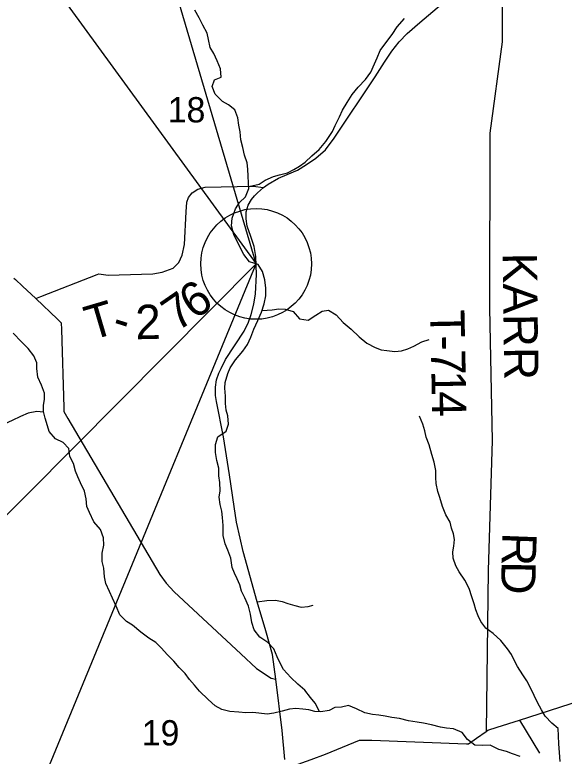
# Model space of a CAD drawing. Extents: x 0 to 34, y 0 to 22.
# Drawn here: x 4.921 to 5.831, y 16.276 to 17.503 of the extents above; entities that cross this region are included whole.
import ezdxf

# ---------------------------------------------------------------- set-up
doc = ezdxf.new("R2010")
doc.units = 0
for name, color, linetype in [('GM_X_County_Road', 7, 'Continuous'), ('GM_X_Minor_River', 7, 'Continuous'), ('GM_X_Section_Text', 7, 'Continuous'), ('GM_X_State_Route', 7, 'Continuous'), ('GM_X_Township_Road', 7, 'Continuous'), ('GM_X_Township_Road_Text', 7, 'Continuous'), ('SH_Text', 7, 'Continuous')]:
    doc.layers.add(name, color=color, linetype=linetype)

msp = doc.modelspace()

# ---------------------------------------------------------------- linework, layer by layer
at = {"layer": 'GM_X_County_Road'}
msp.add_lwpolyline([(5.3691, 16.2545), (5.3828, 16.2597), (5.4119, 16.2704), (5.4359, 16.279), (5.4923, 16.3023), (5.5127, 16.3023), (5.6694, 16.2963), (5.6728, 16.2962), (5.686, 16.3055), (5.702, 16.3168), (5.7051, 16.3189), (5.7202, 16.3238), (5.7575, 16.3358), (6.0466, 16.4289), (6.0506, 16.4302), (6.0602, 16.4422), (6.1578, 16.5648), (6.1712, 16.5792), (6.2848, 16.701), (6.2915, 16.7083)], dxfattribs=at)
at = {"layer": 'GM_X_Minor_River'}
for points in [[(5.4257, 16.3497), (5.4187, 16.3637), (5.4111, 16.3732), (5.4017, 16.385), (5.39, 16.3953), (5.3783, 16.4063), (5.3663, 16.4196), (5.361, 16.4302), (5.3558, 16.4405), (5.3505, 16.4534), (5.3403, 16.4644), (5.3268, 16.4728), (5.3177, 16.4854), (5.3136, 16.4975), (5.3114, 16.5112), (5.3084, 16.5245), (5.302, 16.5381), (5.2964, 16.5491), (5.2938, 16.5598), (5.2897, 16.5696), (5.2848, 16.5791), (5.281, 16.5886), (5.2788, 16.6038), (5.274, 16.6171), (5.2698, 16.6273), (5.2665, 16.6414), (5.2665, 16.6577), (5.2654, 16.6709), (5.264, 16.6816), (5.2614, 16.6926), (5.2595, 16.7047), (5.2611, 16.7153), (5.2607, 16.7293), (5.2593, 16.74), (5.2589, 16.7528), (5.2556, 16.7654), (5.2537, 16.779), (5.2534, 16.7919), (5.2572, 16.8048), (5.2713, 16.8138), (5.2751, 16.8259), (5.274, 16.8392), (5.2714, 16.8487), (5.2699, 16.8597), (5.27, 16.8722), (5.2689, 16.8851), (5.2697, 16.8946), (5.2739, 16.9093), (5.2781, 16.9192), (5.2865, 16.9324), (5.299, 16.9468), (5.3066, 16.9574), (5.3123, 16.9695), (5.3173, 16.9831), (5.3238, 16.9971), (5.3299, 17.0111), (5.3345, 17.0251), (5.3372, 17.0384), (5.3372, 17.0509), (5.3354, 17.0645), (5.3313, 17.0782), (5.3241, 17.09), (5.3101, 17.0946), (5.3004, 17.1067), (5.2958, 17.1162), (5.2842, 17.1398), (5.2801, 17.1538), (5.2813, 17.1667), (5.287, 17.1822), (5.2931, 17.1928), (5.3034, 17.2019), (5.3087, 17.2159), (5.3084, 17.2254), (5.3076, 17.2364), (5.3069, 17.2481), (5.3058, 17.2583), (5.3017, 17.2713), (5.2991, 17.2838), (5.2954, 17.2963), (5.2943, 17.3096), (5.2924, 17.3209), (5.2906, 17.3327), (5.2857, 17.346), (5.2752, 17.3544), (5.2653, 17.3597), (5.2533, 17.3723), (5.248, 17.3848), (5.2522, 17.3958), (5.2628, 17.4003), (5.2621, 17.4139), (5.2561, 17.4272), (5.2509, 17.4394), (5.2449, 17.4496), (5.2419, 17.4625), (5.24, 17.4732), (5.2325, 17.4861), (5.2265, 17.4986), (5.2194, 17.5111)], [(5.3086, 17.2192), (5.3261, 17.223), (5.336, 17.2294), (5.3496, 17.2358), (5.3595, 17.2384), (5.3731, 17.2418), (5.3833, 17.2474), (5.3928, 17.2531), (5.4023, 17.2595), (5.4133, 17.2697), (5.4255, 17.2806), (5.4365, 17.2939), (5.4475, 17.3101), (5.4521, 17.3203), (5.4593, 17.3347), (5.4639, 17.3453), (5.4719, 17.3582), (5.4799, 17.3714), (5.4901, 17.3839), (5.5019, 17.3963), (5.511, 17.4084), (5.5168, 17.4224), (5.5213, 17.4323), (5.5267, 17.4444), (5.5358, 17.4569), (5.5461, 17.4708), (5.5548, 17.4837), (5.5666, 17.4973)], [(5.3308, 17.014), (5.3473, 17.0148), (5.3587, 17.0167), (5.3689, 17.0163), (5.3825, 17.012), (5.393, 16.9999), (5.407, 16.9979), (5.4199, 17.0062), (5.4305, 17.013), (5.4411, 17.0145), (5.4536, 17.0068), (5.4652, 16.9939), (5.4785, 16.9829), (5.4916, 16.9703), (5.5045, 16.9596), (5.5181, 16.9524), (5.5279, 16.9486), (5.5377, 16.9474), (5.5509, 16.9458), (5.5619, 16.9473), (5.5721, 16.9503), (5.5824, 16.9548), (5.5956, 16.9619), (5.6074, 16.9661)], [(5.0255, 16.7382), (5.0217, 16.7481), (5.018, 16.7606), (5.012, 16.7724), (5.0105, 16.7853), (5.0011, 16.7951), (4.9883, 16.8013), (4.9777, 16.8134), (4.9751, 16.8229), (4.9714, 16.8358), (4.9684, 16.8464), (4.9688, 16.8563), (4.97, 16.8673), (4.97, 16.8768), (4.9651, 16.8901), (4.9591, 16.9037), (4.9577, 16.9178), (4.9573, 16.9272), (4.9524, 16.939), (4.943, 16.9508), (4.9321, 16.9618), (4.9185, 16.9763)], [(4.9687, 16.8454), (4.9574, 16.8465), (4.9434, 16.8439), (4.9305, 16.8386), (4.9169, 16.8319), (4.9032, 16.8255), (4.8934, 16.8202), (4.8812, 16.8134), (4.8661, 16.8048), (4.8555, 16.798), (4.8456, 16.7916), (4.8331, 16.7852), (4.8191, 16.7773), (4.8088, 16.7731), (4.7956, 16.7637), (4.78, 16.7547), (4.7705, 16.7509), (4.7577, 16.7449), (4.7467, 16.7427), (4.7221, 16.7371), (4.7119, 16.736), (4.7005, 16.7364)], [(5.825, 16.267), (5.8235, 16.2822), (5.8224, 16.2962), (5.8221, 16.3098), (5.8214, 16.3216), (5.8112, 16.3307), (5.7999, 16.3421), (5.7939, 16.3524), (5.7871, 16.3649), (5.7819, 16.3763), (5.7762, 16.3881), (5.7695, 16.4006), (5.7631, 16.4105), (5.7541, 16.4242), (5.7492, 16.4337), (5.7439, 16.4443), (5.7375, 16.4538), (5.7266, 16.4675), (5.7138, 16.4789), (5.7017, 16.4881), (5.6934, 16.4987), (5.6889, 16.5082), (5.6852, 16.5181), (5.6822, 16.5283), (5.6781, 16.5397), (5.674, 16.5534), (5.6668, 16.5671), (5.6574, 16.5811), (5.6518, 16.591), (5.6477, 16.6039), (5.6469, 16.6141), (5.6485, 16.6236), (5.6497, 16.6346), (5.6478, 16.6441), (5.6448, 16.6536), (5.6422, 16.6634), (5.6351, 16.6756), (5.6298, 16.6896), (5.6253, 16.7041), (5.6223, 16.7143), (5.619, 16.7272), (5.6186, 16.7371), (5.6187, 16.7488), (5.6161, 16.7625), (5.612, 16.7754), (5.6075, 16.7913), (5.6026, 16.8042), (5.6004, 16.8145), (5.5974, 16.8258), (5.5918, 16.8388)], [(5.7584, 16.2752), (5.7456, 16.2798), (5.7358, 16.2836), (5.7233, 16.2871), (5.7089, 16.2943), (5.6961, 16.2936), (5.6836, 16.2941), (5.6711, 16.3036), (5.6621, 16.3154), (5.6481, 16.3211), (5.6364, 16.3223), (5.6266, 16.3238), (5.6115, 16.3281), (5.5982, 16.3308), (5.5876, 16.332), (5.5733, 16.3347), (5.5585, 16.3385), (5.5457, 16.3401), (5.5347, 16.3424), (5.5241, 16.3436), (5.5139, 16.3451), (5.5011, 16.3478), (5.4875, 16.3543), (5.4739, 16.3601), (5.4625, 16.3571), (5.4515, 16.3564), (5.4417, 16.3518), (5.4284, 16.3496), (5.4182, 16.35), (5.4084, 16.3527), (5.3982, 16.3539), (5.3865, 16.3551), (5.3763, 16.3536), (5.3641, 16.3503), (5.3501, 16.3473), (5.3391, 16.3454), (5.3252, 16.347), (5.3153, 16.3482), (5.3036, 16.3478), (5.2923, 16.3486), (5.2771, 16.3498), (5.2639, 16.3533), (5.2533, 16.3594), (5.2416, 16.3697), (5.2273, 16.3834), (5.2186, 16.3936), (5.2104, 16.4031), (5.2032, 16.4127), (5.1934, 16.4229), (5.1847, 16.4332), (5.1734, 16.4442), (5.164, 16.4545), (5.1546, 16.4644), (5.1429, 16.4716), (5.1301, 16.4815), (5.1161, 16.4926), (5.1063, 16.4987), (5.095, 16.5097), (5.089, 16.5245), (5.083, 16.5378), (5.0777, 16.5488), (5.0717, 16.5621), (5.0695, 16.5728), (5.0684, 16.5872), (5.0658, 16.5985), (5.0659, 16.6118), (5.0686, 16.6254), (5.0679, 16.6376), (5.063, 16.6512), (5.0517, 16.6642), (5.0449, 16.6794), (5.0404, 16.6892), (5.0393, 16.7021), (5.0364, 16.715), (5.0296, 16.7283), (5.0255, 16.7382)]]:
    msp.add_lwpolyline(points, dxfattribs=at)
at = {"layer": 'GM_X_State_Route'}
msp.add_lwpolyline([(5.3683, 16.2706), (5.3643, 16.3184), (5.3537, 16.4036), (5.3481, 16.4443), (5.3371, 16.4833), (5.3229, 16.5315), (5.2993, 16.6146), (5.2943, 16.6369), (5.2882, 16.6635), (5.2846, 16.6892), (5.2767, 16.7418), (5.267, 16.8046), (5.2552, 16.8631), (5.2537, 16.8731), (5.2534, 16.8869), (5.2555, 16.8988), (5.2593, 16.91), (5.2629, 16.9177), (5.2703, 16.9325), (5.3009, 16.9798), (5.3083, 16.9946), (5.3129, 17.0073), (5.3172, 17.0241), (5.32, 17.0412), (5.3216, 17.0734), (5.3205, 17.1033), (5.3175, 17.1197), (5.3122, 17.1362), (5.3062, 17.1533), (5.3042, 17.1656), (5.3043, 17.177), (5.3076, 17.1885), (5.3132, 17.1975), (5.3182, 17.2039), (5.3233, 17.2087), (5.333, 17.2174), (5.3408, 17.2233), (5.358, 17.2332), (5.3722, 17.2389), (5.3894, 17.2462), (5.4046, 17.2554), (5.4198, 17.2662), (5.436, 17.2797), (5.4504, 17.2991), (5.5182, 17.4005), (5.5338, 17.4249), (5.5459, 17.4433), (5.5579, 17.4589), (5.5711, 17.4724), (5.592, 17.4906), (5.6638, 17.5521)], dxfattribs=at)
at = {"layer": 'GM_X_Township_Road'}
msp.add_line((5.7575, 16.3358), (5.7904, 16.2809), dxfattribs=at)
for points in [[(5.7281, 17.597), (5.7288, 17.4586), (5.7081, 17.3077), (5.7076, 17.0179), (5.7121, 16.7986), (5.7057, 16.5833), (5.702, 16.3168)], [(4.9556, 17.0336), (4.9641, 17.037), (5.0577, 17.0734), (5.0605, 17.0745), (5.0756, 17.0721), (5.1307, 17.074), (5.1496, 17.0745), (5.1653, 17.0772), (5.1835, 17.0842), (5.1929, 17.0936), (5.1986, 17.1054), (5.2024, 17.1232), (5.2047, 17.1774), (5.206, 17.1932), (5.2088, 17.2011), (5.2151, 17.2087), (5.2243, 17.2146), (5.2363, 17.2182), (5.3162, 17.2195), (5.333, 17.2174)], [(4.9192, 17.0675), (4.9224, 17.065), (4.9339, 17.0541), (4.9556, 17.0336), (4.9917, 16.9995), (4.9979, 16.9935), (4.9983, 16.9823), (5.0023, 16.8531), (5.0025, 16.8466), (5.0088, 16.8348), (5.1615, 16.5767), (5.172, 16.5624), (5.1853, 16.5478), (5.2956, 16.4455), (5.3216, 16.4213), (5.3459, 16.4049), (5.3537, 16.4036)], [(5.3229, 16.5315), (5.3385, 16.5338), (5.3532, 16.5341), (5.3638, 16.5318), (5.3736, 16.5289), (5.3852, 16.5254), (5.3956, 16.5228), (5.4069, 16.5238), (5.4153, 16.5261)]]:
    msp.add_lwpolyline(points, dxfattribs=at)
at = {"layer": 'SH_Text'}
for points in [[(5.3209, 17.091), (4.9408, 18.3776), (4.9408, 17.6129)], [(4.7911, 16.5585), (4.7911, 15.8085), (5.3209, 17.091)]]:
    msp.add_lwpolyline(points, close=True, dxfattribs=at)
msp.add_circle((5.3209, 17.091), 0.0917, dxfattribs=at)

# ---------------------------------------------------------------- texts
at = {"layer": 'GM_X_Section_Text'}
for s, p in [('18', (5.1745, 17.3253)), ('19', (5.1315, 16.2937))]:
    msp.add_text(s, height=0.04186, rotation=0, dxfattribs=at).set_placement(p)
at = {"layer": 'GM_X_Township_Road_Text'}
for s, height, rotation, p in [('KARR', 0.05682, 270.7324, (5.7294, 17.1093)), ('6', 0.0568, 34.0518, (5.2183, 16.9975)), ('7', 0.0568, 34.612, (5.1899, 16.9778)), ('T', 0.0568, 16.4327, (5.0472, 16.9641)), ('2', 0.0568, 1.1983, (5.1213, 16.9662)), ('T', 0.0568, 271.1851, (5.6093, 17.0145)), ('-', 0.0568, 342.1953, (5.079, 16.9762)), ('-', 0.0568, 271.1841, (5.6101, 16.9721)), ('7', 0.0568, 271.1678, (5.6106, 16.949)), ('1', 0.0568, 271.0424, (5.6113, 16.9143)), ('4', 0.0568, 270.8163, (5.612, 16.8797)), ('R', 0.0568, 267.8685, (5.7294, 16.6469)), ('D', 0.0568, 269.1867, (5.7277, 16.5989))]:
    msp.add_text(s, height=height, rotation=rotation, dxfattribs=at).set_placement(p)

doc.saveas('drawing.dxf')
